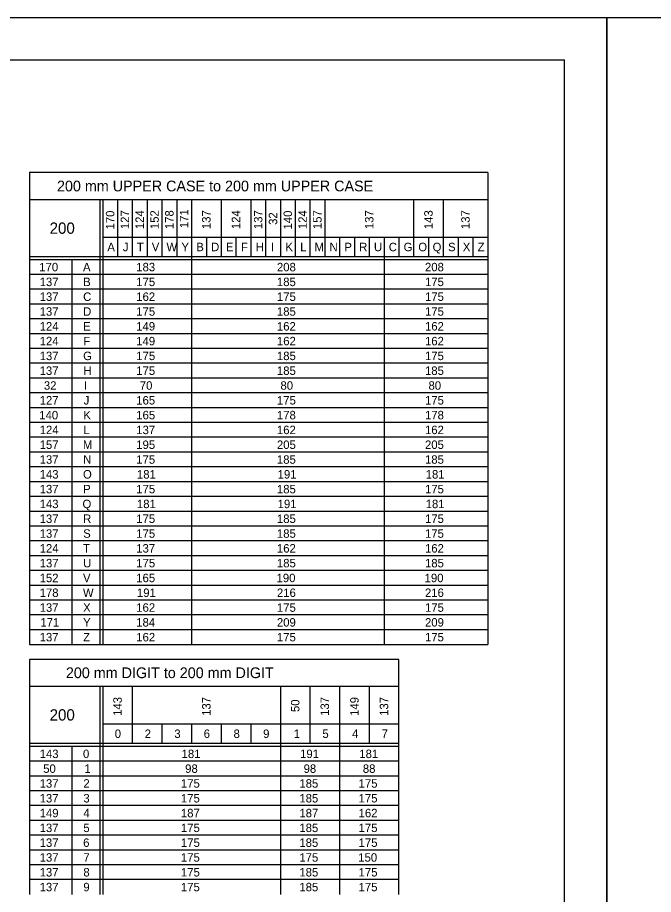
# Model space of a CAD drawing. Extents: x 637580 to 641849, y 297270 to 299646.
# Drawn here: x 639053.4 to 639278.9, y 299334.6 to 299645.6 of the extents above; entities that cross this region are included whole.
import ezdxf

# ---------------------------------------------------------------- set-up
doc = ezdxf.new("R2010")
doc.units = 0
for name, color, linetype in [('1', 7, 'Continuous'), ('2', 7, 'Continuous'), ('XCS-GRID-HVGL', 7, 'Continuous')]:
    doc.layers.add(name, color=color, linetype=linetype)

msp = doc.modelspace()

# ---------------------------------------------------------------- linework, layer by layer
at = {"layer": '1'}
for p in [(638461.31, 299630.63), (639247.31, 299066.63)]:
    msp.add_line(p, (639247.31, 299630.63), dxfattribs=at)
at = {"layer": '2'}
for p, q in [((639220.11, 299590.63), (639057.61, 299590.63)), ((639057.61, 299590.63), (639057.61, 299423.25)), ((639220.11, 299590.63), (639220.11, 299423.25)), ((639057.61, 299581.13), (639220.11, 299581.13)), ((639082.61, 299581.13), (639082.61, 299423.25)), ((639083.61, 299581.13), (639083.61, 299423.25)), ((639088.86, 299581.13), (639088.86, 299560.75)), ((639094.11, 299581.13), (639094.11, 299560.75)), ((639099.36, 299581.13), (639099.36, 299560.75)), ((639104.61, 299581.13), (639104.61, 299560.75)), ((639109.86, 299581.13), (639109.86, 299560.75)), ((639115.11, 299581.13), (639115.11, 299423.25)), ((639125.61, 299581.13), (639125.61, 299560.75)), ((639136.11, 299581.13), (639136.11, 299560.75)), ((639141.36, 299581.13), (639141.36, 299560.75)), ((639146.61, 299581.13), (639146.61, 299560.75)), ((639151.86, 299581.13), (639151.86, 299560.75)), ((639157.11, 299581.13), (639157.11, 299560.75)), ((639162.36, 299581.13), (639162.36, 299560.75)), ((639193.86, 299581.13), (639193.86, 299560.75)), ((639204.36, 299581.13), (639204.36, 299560.75)), ((639083.61, 299567.75), (639220.11, 299567.75)), ((639120.36, 299567.75), (639120.36, 299560.75)), ((639130.86, 299567.75), (639130.86, 299560.75)), ((639167.61, 299567.75), (639167.61, 299560.75)), ((639172.86, 299567.75), (639172.86, 299560.75)), ((639178.11, 299567.75), (639178.11, 299560.75)), ((639178.11, 299567.75), (639178.11, 299560.75)), ((639183.36, 299567.75), (639183.36, 299423.25)), ((639188.61, 299567.75), (639188.61, 299560.75)), ((639199.11, 299567.75), (639199.11, 299560.75)), ((639209.61, 299567.75), (639209.61, 299560.75)), ((639214.86, 299567.75), (639214.86, 299560.75)), ((639220.11, 299560.75), (639057.61, 299560.75)), ((639220.11, 299559.75), (639057.61, 299559.75)), ((639072.61, 299559.75), (639072.61, 299423.25)), ((639220.11, 299554.5), (639057.61, 299554.5)), ((639220.11, 299549.25), (639057.61, 299549.25)), ((639220.11, 299544), (639057.61, 299544)), ((639220.11, 299538.75), (639057.61, 299538.75)), ((639220.11, 299533.5), (639057.61, 299533.5)), ((639220.11, 299528.25), (639057.61, 299528.25)), ((639220.11, 299523), (639057.61, 299523)), ((639220.11, 299517.75), (639057.61, 299517.75)), ((639220.11, 299512.5), (639057.61, 299512.5)), ((639220.11, 299507.25), (639057.61, 299507.25)), ((639220.11, 299502), (639057.61, 299502)), ((639220.11, 299496.75), (639057.61, 299496.75)), ((639220.11, 299491.5), (639057.61, 299491.5)), ((639220.11, 299486.25), (639057.61, 299486.25)), ((639220.11, 299481), (639057.61, 299481)), ((639220.11, 299475.75), (639057.61, 299475.75)), ((639220.11, 299470.5), (639057.61, 299470.5)), ((639220.11, 299465.25), (639057.61, 299465.25)), ((639220.11, 299460), (639057.61, 299460)), ((639220.11, 299454.75), (639057.61, 299454.75)), ((639220.11, 299449.5), (639057.61, 299449.5)), ((639220.11, 299444.25), (639057.61, 299444.25)), ((639220.11, 299439), (639057.61, 299439)), ((639220.11, 299433.75), (639057.61, 299433.75)), ((639220.11, 299428.5), (639057.61, 299428.5)), ((639057.61, 299423.25), (639057.61, 299423.25)), ((639057.61, 299423.25), (639220.11, 299423.25)), ((639188.61, 299418), (639057.61, 299418)), ((639057.61, 299418), (639057.61, 299334.63)), ((639188.61, 299334.63), (639188.61, 299418)), ((639057.61, 299408.5), (639188.61, 299408.5)), ((639082.61, 299408.5), (639082.61, 299334.63)), ((639083.61, 299408.5), (639083.61, 299334.63)), ((639094.11, 299408.5), (639094.11, 299388.13)), ((639146.61, 299408.5), (639146.61, 299334.63)), ((639157.11, 299408.5), (639157.11, 299388.13)), ((639167.61, 299408.5), (639167.61, 299334.63)), ((639178.11, 299408.5), (639178.11, 299388.13)), ((639083.61, 299395.13), (639188.61, 299395.13)), ((639104.61, 299395.13), (639104.61, 299388.13)), ((639115.11, 299395.13), (639115.11, 299388.13)), ((639125.61, 299395.13), (639125.61, 299388.13)), ((639136.11, 299395.13), (639136.11, 299388.13)), ((639188.61, 299388.13), (639057.61, 299388.13)), ((639188.61, 299387.13), (639057.61, 299387.13)), ((639072.61, 299387.13), (639072.61, 299334.63)), ((639188.61, 299381.88), (639057.61, 299381.88)), ((639188.61, 299376.63), (639057.61, 299376.63)), ((639188.61, 299371.38), (639057.61, 299371.38)), ((639188.61, 299366.13), (639057.61, 299366.13)), ((639188.61, 299360.88), (639057.61, 299360.88)), ((639188.61, 299355.63), (639057.61, 299355.63)), ((639188.61, 299350.38), (639057.61, 299350.38)), ((639188.61, 299345.13), (639057.61, 299345.13)), ((639188.61, 299339.88), (639057.61, 299339.88))]:
    msp.add_line(p, q, dxfattribs=at)
at = {"layer": 'XCS-GRID-HVGL'}
for points in [[(638421.31, 299645.63), (639262.31, 299645.63), (639262.31, 299051.63), (638421.31, 299051.63)], [(639262.31, 299645.63), (640103.31, 299645.63), (640103.31, 299051.63), (639262.31, 299051.63)]]:
    msp.add_lwpolyline(points, close=True, dxfattribs=at)

# ---------------------------------------------------------------- texts
at = {"layer": '2'}
for s, height, p in [('200 mm UPPER CASE to 200 mm UPPER CASE', 3.8, (639067.4, 299583.98)), ('200', 4, (639064.8, 299568.94)), ('A', 3, (639085.26, 299562.75)), ('J', 3, (639090.74, 299562.75)), ('T', 3, (639095.74, 299562.75)), ('V', 3, (639101.01, 299562.75)), ('W', 3, (639106.23, 299562.75)), ('Y', 3, (639111.54, 299562.75)), ('B', 3, (639116.8, 299562.75)), ('D', 3, (639122.05, 299562.75)), ('E', 3, (639127.32, 299562.75)), ('F', 3, (639132.62, 299562.75)), ('H', 3, (639137.89, 299562.75)), ('I', 3, (639143.3, 299562.75)), ('K', 3, (639148.39, 299562.75)), ('L', 3, (639153.64, 299562.75)), ('M', 3, (639158.73, 299562.75)), ('N', 3, (639164.05, 299562.75)), ('P', 3, (639169.3, 299562.75)), ('R', 3, (639174.55, 299562.75)), ('U', 3, (639179.79, 299562.75)), ('C', 3, (639185.05, 299562.75)), ('G', 3, (639190.3, 299562.75)), ('O', 3, (639195.51, 299562.75)), ('Q', 3, (639200.58, 299562.75)), ('S', 3, (639206.07, 299562.75)), ('X', 3, (639211.29, 299562.75)), ('Z', 3, (639216.55, 299562.75)), ('170', 3, (639061.13, 299555.63)), ('A', 3, (639076.63, 299555.63)), ('183', 3, (639095.51, 299555.63)), ('208', 3, (639145.39, 299555.63)), ('208', 3, (639197.89, 299555.63)), ('137', 3, (639061.26, 299550.38)), ('B', 3, (639076.68, 299550.38)), ('175', 3, (639095.51, 299550.38)), ('185', 3, (639145.39, 299550.38)), ('175', 3, (639197.89, 299550.38)), ('137', 3, (639061.26, 299545.13)), ('C', 3, (639076.68, 299545.13)), ('162', 3, (639095.51, 299545.13)), ('175', 3, (639145.39, 299545.13)), ('175', 3, (639197.89, 299545.13)), ('137', 3, (639061.26, 299539.88)), ('D', 3, (639076.68, 299539.88)), ('175', 3, (639095.51, 299539.88)), ('185', 3, (639145.39, 299539.88)), ('175', 3, (639197.89, 299539.88)), ('124', 3, (639061.26, 299534.63)), ('E', 3, (639076.69, 299534.63)), ('149', 3, (639095.51, 299534.63)), ('162', 3, (639145.39, 299534.63)), ('162', 3, (639197.89, 299534.63)), ('124', 3, (639061.26, 299529.38)), ('F', 3, (639076.75, 299529.38)), ('149', 3, (639095.51, 299529.38)), ('162', 3, (639145.39, 299529.38)), ('162', 3, (639197.89, 299529.38)), ('137', 3, (639061.26, 299524.13)), ('G', 3, (639076.68, 299524.13)), ('175', 3, (639095.51, 299524.13)), ('185', 3, (639145.39, 299524.13)), ('175', 3, (639197.89, 299524.13)), ('137', 3, (639061.26, 299518.88)), ('H', 3, (639076.76, 299518.88)), ('175', 3, (639095.51, 299518.88)), ('185', 3, (639145.39, 299518.88)), ('185', 3, (639197.89, 299518.88)), ('32', 3, (639062.76, 299513.63)), ('I', 3, (639076.93, 299513.63)), ('70', 3, (639096.76, 299513.63)), ('80', 3, (639146.64, 299513.63)), ('80', 3, (639199.14, 299513.63)), ('127', 3, (639061.26, 299508.38)), ('J', 3, (639076.87, 299508.38)), ('165', 3, (639095.51, 299508.38)), ('175', 3, (639145.39, 299508.38)), ('175', 3, (639197.89, 299508.38)), ('140', 3, (639061.13, 299503.13)), ('K', 3, (639076.76, 299503.13)), ('165', 3, (639095.51, 299503.13)), ('178', 3, (639145.39, 299503.13)), ('178', 3, (639197.89, 299503.13)), ('124', 3, (639061.26, 299497.88)), ('L', 3, (639076.76, 299497.88)), ('137', 3, (639095.51, 299497.88)), ('162', 3, (639145.39, 299497.88)), ('162', 3, (639197.89, 299497.88)), ('157', 3, (639061.26, 299492.63)), ('M', 3, (639076.61, 299492.63)), ('195', 3, (639095.51, 299492.63)), ('205', 3, (639145.39, 299492.63)), ('205', 3, (639197.89, 299492.63)), ('137', 3, (639061.26, 299487.38)), ('N', 3, (639076.68, 299487.38)), ('175', 3, (639095.51, 299487.38)), ('185', 3, (639145.39, 299487.38)), ('185', 3, (639197.89, 299487.38)), ('143', 3, (639061.26, 299482.13)), ('O', 3, (639076.63, 299482.13)), ('181', 3, (639095.76, 299482.13)), ('191', 3, (639145.64, 299482.13)), ('181', 3, (639198.14, 299482.13)), ('137', 3, (639061.26, 299476.88)), ('P', 3, (639076.68, 299476.88)), ('175', 3, (639095.51, 299476.88)), ('185', 3, (639145.39, 299476.88)), ('175', 3, (639197.89, 299476.88)), ('143', 3, (639061.26, 299471.63)), ('Q', 3, (639076.45, 299471.63)), ('181', 3, (639095.76, 299471.63)), ('191', 3, (639145.64, 299471.63)), ('181', 3, (639198.14, 299471.63)), ('137', 3, (639061.26, 299466.38)), ('R', 3, (639076.68, 299466.38)), ('175', 3, (639095.51, 299466.38)), ('185', 3, (639145.39, 299466.38)), ('175', 3, (639197.89, 299466.38)), ('137', 3, (639061.26, 299461.13)), ('S', 3, (639076.69, 299461.13)), ('175', 3, (639095.51, 299461.13)), ('185', 3, (639145.39, 299461.13)), ('175', 3, (639197.89, 299461.13)), ('124', 3, (639061.26, 299455.88)), ('T', 3, (639076.62, 299455.88)), ('137', 3, (639095.51, 299455.88)), ('162', 3, (639145.39, 299455.88)), ('162', 3, (639197.89, 299455.88)), ('137', 3, (639061.26, 299450.63)), ('U', 3, (639076.67, 299450.63)), ('175', 3, (639095.51, 299450.63)), ('185', 3, (639145.39, 299450.63)), ('185', 3, (639197.89, 299450.63)), ('152', 3, (639061.26, 299445.38)), ('V', 3, (639076.63, 299445.38)), ('165', 3, (639095.51, 299445.38)), ('190', 3, (639145.26, 299445.38)), ('190', 3, (639197.76, 299445.38)), ('178', 3, (639061.26, 299440.13)), ('W', 3, (639076.61, 299440.13)), ('191', 3, (639095.76, 299440.13)), ('216', 3, (639145.39, 299440.13)), ('216', 3, (639197.89, 299440.13)), ('137', 3, (639061.26, 299434.88)), ('X', 3, (639076.67, 299434.88)), ('162', 3, (639095.51, 299434.88)), ('175', 3, (639145.39, 299434.88)), ('175', 3, (639197.89, 299434.88)), ('171', 3, (639061.51, 299429.63)), ('Y', 3, (639076.67, 299429.63)), ('184', 3, (639095.51, 299429.63)), ('209', 3, (639145.39, 299429.63)), ('209', 3, (639197.89, 299429.63)), ('137', 3, (639061.26, 299424.38)), ('Z', 3, (639076.68, 299424.38)), ('162', 3, (639095.51, 299424.38)), ('175', 3, (639145.39, 299424.38)), ('175', 3, (639197.89, 299424.38)), ('200 mm DIGIT to 200 mm DIGIT', 3.8, (639070.56, 299411.35)), ('200', 4, (639064.8, 299396.31)), ('0', 3, (639087.88, 299390.13)), ('2', 3, (639098.51, 299390.13)), ('3', 3, (639109.01, 299390.13)), ('6', 3, (639119.43, 299390.13)), ('8', 3, (639130.01, 299390.13)), ('9', 3, (639140.5, 299390.13)), ('1', 3, (639151.35, 299390.13)), ('5', 3, (639161.51, 299390.13)), ('4', 3, (639172.01, 299390.13)), ('7', 3, (639182.51, 299390.13)), ('143', 3, (639061.26, 299383)), ('0', 3, (639076.63, 299383)), ('181', 3, (639111.6, 299383)), ('191', 3, (639153.6, 299383)), ('181', 3, (639174.6, 299383)), ('50', 3, (639062.51, 299377.75)), ('1', 3, (639077.1, 299377.75)), ('98', 3, (639112.85, 299377.75)), ('98', 3, (639154.85, 299377.75)), ('88', 3, (639175.85, 299377.75)), ('137', 3, (639061.26, 299372.5)), ('2', 3, (639076.76, 299372.5)), ('175', 3, (639111.35, 299372.5)), ('185', 3, (639153.35, 299372.5)), ('175', 3, (639174.35, 299372.5)), ('137', 3, (639061.26, 299367.25)), ('3', 3, (639076.76, 299367.25)), ('175', 3, (639111.35, 299367.25)), ('185', 3, (639153.35, 299367.25)), ('175', 3, (639174.35, 299367.25)), ('149', 3, (639061.26, 299362)), ('4', 3, (639076.76, 299362)), ('187', 3, (639111.35, 299362)), ('187', 3, (639153.35, 299362)), ('162', 3, (639174.35, 299362)), ('137', 3, (639061.26, 299356.75)), ('5', 3, (639076.76, 299356.75)), ('175', 3, (639111.35, 299356.75)), ('185', 3, (639153.35, 299356.75)), ('175', 3, (639174.35, 299356.75)), ('137', 3, (639061.26, 299351.5)), ('6', 3, (639076.68, 299351.5)), ('175', 3, (639111.35, 299351.5)), ('185', 3, (639153.35, 299351.5)), ('175', 3, (639174.35, 299351.5)), ('137', 3, (639061.26, 299346.25)), ('7', 3, (639076.76, 299346.25)), ('175', 3, (639111.35, 299346.25)), ('175', 3, (639153.35, 299346.25)), ('150', 3, (639174.23, 299346.25)), ('137', 3, (639061.26, 299341)), ('8', 3, (639076.76, 299341)), ('175', 3, (639111.35, 299341)), ('185', 3, (639153.35, 299341)), ('175', 3, (639174.35, 299341)), ('137', 3, (639061.26, 299335.75)), ('9', 3, (639076.75, 299335.75)), ('175', 3, (639111.35, 299335.75)), ('185', 3, (639153.35, 299335.75)), ('175', 3, (639174.35, 299335.75))]:
    msp.add_text(s, height=height, dxfattribs=at).set_placement(p)
for s, p in [('127', (639092.99, 299570.59)), ('124', (639098.24, 299570.59)), ('152', (639103.49, 299570.59)), ('178', (639108.74, 299570.59)), ('171', (639113.99, 299570.93)), ('137', (639121.86, 299570.59)), ('124', (639132.36, 299570.59)), ('137', (639140.24, 299570.59)), ('124', (639155.99, 299570.59)), ('157', (639161.24, 299570.59)), ('137', (639179.61, 299570.59)), ('143', (639200.61, 299570.59)), ('137', (639213.74, 299570.59)), ('170', (639087.74, 299570.46)), ('32', (639145.49, 299572.09)), ('140', (639150.74, 299570.46)), ('143', (639090.36, 299397.96)), ('137', (639121.86, 299397.96)), ('50', (639153.36, 299399.33)), ('137', (639163.86, 299397.96)), ('149', (639174.36, 299397.95)), ('137', (639184.86, 299397.96))]:
    msp.add_text(s, height=3, rotation=90, dxfattribs=at).set_placement(p)

doc.saveas('drawing.dxf')
